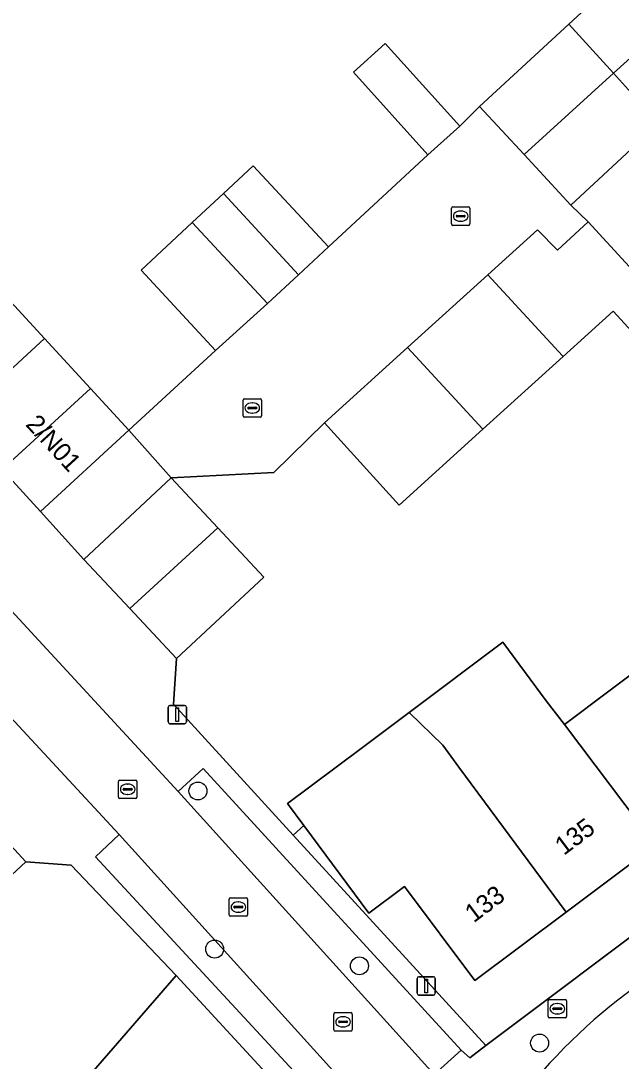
# Model space of a CAD drawing. Extents: x 158472 to 159562, y 388525 to 389606.
# Drawn here: x 159022.2 to 159054.8, y 388854.3 to 388910.9 of the extents above; entities that cross this region are included whole.
import ezdxf

# ---------------------------------------------------------------- set-up
doc = ezdxf.new("R2010")
doc.units = 0
for name, color, linetype in [('IMGEO_Boom', 7, 'Continuous'), ('IMGEO_Brandkraan', 7, 'Continuous'), ('IMGEO_Erf', 7, 'Continuous'), ('IMGEO_Kolk', 7, 'Continuous'), ('IMGEO_Lichtmast', 7, 'Continuous'), ('IMGEO_Muur', 7, 'Continuous'), ('IMGEO_Pand', 7, 'Continuous'), ('IMGEO_Pand_nummerreeks', 7, 'Continuous'), ('IMGEO_Parkeervlak_open', 7, 'Continuous'), ('IMGEO_Rijbaan_lokaal_open', 7, 'Continuous'), ('IMGEO_Voetpad_open', 7, 'Continuous')]:
    doc.layers.add(name, color=color, linetype=linetype)

msp = doc.modelspace()

# ---------------------------------------------------------------- linework, layer by layer
at = {"layer": 'IMGEO_Boom'}
for centre in [(159031.83, 388869.01), (159032.739, 388860.409), (159040.613, 388859.499), (159050.411, 388855.297)]:
    msp.add_circle(centre, 0.489, dxfattribs=at)
at = {"layer": 'IMGEO_Brandkraan'}
for p, q in [((159050.872, 388856.738), (159050.872, 388857.59)), ((159050.947, 388857.664), (159051.799, 388857.664)), ((159051.131, 388857.158), (159051.131, 388857.17)), ((159051.569, 388857.121), (159051.171, 388857.121)), ((159051.174, 388857.207), (159051.572, 388857.207)), ((159051.36, 388857.444), (159051.385, 388857.444)), ((159051.615, 388857.17), (159051.615, 388857.158)), ((159051.873, 388857.59), (159051.873, 388856.738)), ((159051.799, 388856.664), (159050.947, 388856.664)), ((159051.383, 388856.884), (159051.358, 388856.884))]:
    msp.add_line(p, q, dxfattribs=at)
for points in [[(159050.872, 388856.738), (159050.872, 388857.59)], [(159050.947, 388857.664), (159051.799, 388857.664)], [(159051.873, 388857.59), (159051.873, 388856.738)], [(159051.799, 388856.664), (159050.947, 388856.664)]]:
    msp.add_lwpolyline(points, dxfattribs=at)
for centre, radius, start, end in [((159050.949, 388857.588), 0.0765, 91.552, 178.448), ((159050.949, 388857.588), 0.0765, 91.552, 178.448), ((159051.171, 388857.167), 0.0403, 85.8775, 175.7526), ((159051.168, 388857.157), 0.0366, 178.938, 274.7102), ((159051.572, 388857.164), 0.043, 264.8664, 352.4533), ((159051.576, 388857.169), 0.0386, 1.7309, 96.639), ((159051.797, 388857.588), 0.0765, 1.552, 88.448), ((159051.797, 388857.588), 0.0765, 1.552, 88.448), ((159050.949, 388856.74), 0.0765, 181.552, 268.448), ((159050.949, 388856.74), 0.0765, 181.552, 268.448), ((159051.797, 388856.74), 0.0765, 271.552, 358.448), ((159051.797, 388856.74), 0.0765, 271.552, 358.448)]:
    msp.add_arc(centre, radius, start, end, dxfattribs=at)
for centre, major_axis, ratio, start_param, end_param in [((159051.359, 388857.164), (-0.387, 0.002), 0.722429, 4.712389, 7.853982), ((159051.384, 388857.164), (-0.39, 0.002), 0.717154, 1.570796, 4.712389)]:
    msp.add_ellipse(centre, major_axis=major_axis, ratio=ratio, start_param=start_param, end_param=end_param, dxfattribs=at)
at = {"layer": 'IMGEO_Erf'}
for points in [[(158997.065, 388911.51), (159000.837, 388907.412), (159006.203, 388901.581), (159006.027, 388900.273), (159014.937, 388890.629), (159016.222, 388891.875), (159021.022, 388896.297), (159023.484, 388893.624), (159025.982, 388890.912), (159028.075, 388888.641), (159032.79, 388892.979), (159028.735, 388897.342), (159031.517, 388899.927), (159033.216, 388901.506), (159034.832, 388903.008), (159038.924, 388898.606), (159044.34, 388903.612), (159040.28, 388908.103), (159042.012, 388909.668), (159046.071, 388905.177), (159047.144, 388906.244), (159051.996, 388910.732), (159056.776, 388915.153)], [(159056.892, 388905.314), (159052.102, 388900.883), (159053.054, 388899.965), (159057.103, 388895.546)], [(159055.425, 388894.008), (159054.409, 388895.117), (159051.69, 388892.651), (159047.327, 388888.694), (159042.774, 388884.565), (159038.715, 388889.033), (159035.965, 388886.336), (159030.379, 388886.043), (159032.915, 388883.328), (159035.419, 388880.648), (159030.671, 388876.212), (159030.494, 388873.729), (159037.009, 388866.608), (159047.484, 388855.159), (159067.671, 388870.326)], [(159056.712, 388866.061), (159051.849, 388862.421), (159046.884, 388858.706), (159043.055, 388863.822), (159041.119, 388862.372), (159037.584, 388867.135), (159036.696, 388868.331), (159040.699, 388871.328), (159043.307, 388873.28), (159048.406, 388877.097), (159050.766, 388873.917), (159051.756, 388872.635), (159056.585, 388876.249)], [(159025.441, 388852.975), (159030.636, 388858.979), (159024.943, 388864.972), (159022.471, 388865.149), (159017.646, 388860.705), (159017.52, 388860.589), (159015.056, 388863.265), (159012.581, 388865.952), (159009.531, 388858.308), (159014.028, 388854.382), (159010.166, 388849.906)]]:
    msp.add_lwpolyline(points, dxfattribs=at)
msp.add_lwpolyline([(159025.631, 388881.607), (159030.379, 388886.043), (159028.075, 388888.641), (159023.276, 388884.219)], close=True, dxfattribs=at)
at = {"layer": 'IMGEO_Kolk'}
for p, q in [((159045.619, 388899.854), (159045.619, 388900.706)), ((159045.694, 388900.78), (159046.546, 388900.78)), ((159046.62, 388900.706), (159046.62, 388899.854)), ((159045.878, 388900.274), (159045.878, 388900.286)), ((159046.316, 388900.237), (159045.918, 388900.237)), ((159045.921, 388900.323), (159046.319, 388900.323)), ((159046.107, 388900.56), (159046.132, 388900.56)), ((159046.362, 388900.286), (159046.362, 388900.274)), ((159046.546, 388899.78), (159045.694, 388899.78)), ((159046.13, 388900), (159046.105, 388900)), ((159034.283, 388889.418), (159034.283, 388890.27)), ((159034.358, 388890.344), (159035.21, 388890.344)), ((159034.771, 388890.124), (159034.796, 388890.124)), ((159035.284, 388890.27), (159035.284, 388889.418)), ((159034.542, 388889.838), (159034.542, 388889.85)), ((159034.98, 388889.801), (159034.582, 388889.801)), ((159034.585, 388889.887), (159034.983, 388889.887)), ((159034.794, 388889.564), (159034.769, 388889.564)), ((159035.026, 388889.85), (159035.026, 388889.838)), ((159035.21, 388889.344), (159034.358, 388889.344)), ((159027.584, 388869.604), (159028.436, 388869.604)), ((159027.509, 388868.678), (159027.509, 388869.53)), ((159027.768, 388869.098), (159027.768, 388869.11)), ((159028.206, 388869.061), (159027.808, 388869.061)), ((159027.811, 388869.147), (159028.209, 388869.147)), ((159027.997, 388869.384), (159028.022, 388869.384)), ((159028.252, 388869.11), (159028.252, 388869.098)), ((159028.51, 388869.53), (159028.51, 388868.678)), ((159028.436, 388868.604), (159027.584, 388868.604)), ((159028.02, 388868.824), (159027.995, 388868.824)), ((159033.529, 388862.268), (159033.529, 388863.12)), ((159033.604, 388863.194), (159034.456, 388863.194)), ((159034.017, 388862.974), (159034.042, 388862.974)), ((159034.53, 388863.12), (159034.53, 388862.268)), ((159033.788, 388862.688), (159033.788, 388862.7)), ((159034.226, 388862.651), (159033.828, 388862.651)), ((159033.831, 388862.737), (159034.229, 388862.737)), ((159034.04, 388862.414), (159034.015, 388862.414)), ((159034.272, 388862.7), (159034.272, 388862.688)), ((159034.456, 388862.194), (159033.604, 388862.194)), ((159039.221, 388856.026), (159039.221, 388856.878)), ((159039.296, 388856.952), (159040.148, 388856.952)), ((159039.709, 388856.732), (159039.734, 388856.732)), ((159040.222, 388856.878), (159040.222, 388856.026)), ((159039.48, 388856.446), (159039.48, 388856.458)), ((159039.918, 388856.409), (159039.52, 388856.409)), ((159039.523, 388856.495), (159039.921, 388856.495)), ((159039.732, 388856.172), (159039.707, 388856.172)), ((159039.964, 388856.458), (159039.964, 388856.446)), ((159040.148, 388855.952), (159039.296, 388855.952))]:
    msp.add_line(p, q, dxfattribs=at)
for points in [[(159045.619, 388899.854), (159045.619, 388900.706)], [(159045.694, 388900.78), (159046.546, 388900.78)], [(159046.62, 388900.706), (159046.62, 388899.854)], [(159046.546, 388899.78), (159045.694, 388899.78)], [(159034.283, 388889.418), (159034.283, 388890.27)], [(159034.358, 388890.344), (159035.21, 388890.344)], [(159035.284, 388890.27), (159035.284, 388889.418)], [(159035.21, 388889.344), (159034.358, 388889.344)], [(159027.584, 388869.604), (159028.436, 388869.604)], [(159027.509, 388868.678), (159027.509, 388869.53)], [(159028.51, 388869.53), (159028.51, 388868.678)], [(159028.436, 388868.604), (159027.584, 388868.604)], [(159033.529, 388862.268), (159033.529, 388863.12)], [(159033.604, 388863.194), (159034.456, 388863.194)], [(159034.53, 388863.12), (159034.53, 388862.268)], [(159034.456, 388862.194), (159033.604, 388862.194)], [(159039.221, 388856.026), (159039.221, 388856.878)], [(159039.296, 388856.952), (159040.148, 388856.952)], [(159040.222, 388856.878), (159040.222, 388856.026)], [(159040.148, 388855.952), (159039.296, 388855.952)]]:
    msp.add_lwpolyline(points, dxfattribs=at)
for centre, radius, start, end in [((159045.696, 388900.704), 0.0765, 91.552, 178.448), ((159045.696, 388900.704), 0.0765, 91.552, 178.448), ((159046.544, 388900.704), 0.0765, 1.552, 88.448), ((159046.544, 388900.704), 0.0765, 1.552, 88.448), ((159045.918, 388900.283), 0.0403, 85.8775, 175.7526), ((159045.915, 388900.273), 0.0366, 178.938, 274.7102), ((159046.319, 388900.28), 0.043, 264.8664, 352.4533), ((159046.323, 388900.285), 0.0386, 1.7309, 96.639), ((159045.696, 388899.856), 0.0765, 181.552, 268.448), ((159045.696, 388899.856), 0.0765, 181.552, 268.448), ((159046.544, 388899.856), 0.0765, 271.552, 358.448), ((159046.544, 388899.856), 0.0765, 271.552, 358.448), ((159034.36, 388890.268), 0.0765, 91.552, 178.448), ((159034.36, 388890.268), 0.0765, 91.552, 178.448), ((159035.208, 388890.268), 0.0765, 1.552, 88.448), ((159035.208, 388890.268), 0.0765, 1.552, 88.448), ((159034.36, 388889.42), 0.0765, 181.552, 268.448), ((159034.36, 388889.42), 0.0765, 181.552, 268.448), ((159034.582, 388889.847), 0.0403, 85.8775, 175.7526), ((159034.579, 388889.837), 0.0366, 178.938, 274.7102), ((159034.983, 388889.844), 0.043, 264.8664, 352.4533), ((159034.987, 388889.849), 0.0386, 1.7309, 96.639), ((159035.208, 388889.42), 0.0765, 271.552, 358.448), ((159035.208, 388889.42), 0.0765, 271.552, 358.448), ((159027.586, 388869.528), 0.0765, 91.552, 178.448), ((159027.586, 388869.528), 0.0765, 91.552, 178.448), ((159028.434, 388869.528), 0.0765, 1.552, 88.448), ((159028.434, 388869.528), 0.0765, 1.552, 88.448), ((159027.808, 388869.107), 0.0403, 85.8775, 175.7526), ((159027.805, 388869.097), 0.0366, 178.938, 274.7102), ((159028.209, 388869.104), 0.043, 264.8664, 352.4533), ((159028.213, 388869.109), 0.0386, 1.7309, 96.639), ((159027.586, 388868.68), 0.0765, 181.552, 268.448), ((159027.586, 388868.68), 0.0765, 181.552, 268.448), ((159028.434, 388868.68), 0.0765, 271.552, 358.448), ((159028.434, 388868.68), 0.0765, 271.552, 358.448), ((159033.606, 388863.118), 0.0765, 91.552, 178.448), ((159033.606, 388863.118), 0.0765, 91.552, 178.448), ((159034.454, 388863.118), 0.0765, 1.552, 88.448), ((159034.454, 388863.118), 0.0765, 1.552, 88.448), ((159033.606, 388862.27), 0.0765, 181.552, 268.448), ((159033.606, 388862.27), 0.0765, 181.552, 268.448), ((159033.828, 388862.697), 0.0403, 85.8775, 175.7526), ((159033.825, 388862.687), 0.0366, 178.938, 274.7102), ((159034.229, 388862.694), 0.043, 264.8664, 352.4533), ((159034.233, 388862.699), 0.0386, 1.7309, 96.639), ((159034.454, 388862.27), 0.0765, 271.552, 358.448), ((159034.454, 388862.27), 0.0765, 271.552, 358.448), ((159039.298, 388856.876), 0.0765, 91.552, 178.448), ((159039.298, 388856.876), 0.0765, 91.552, 178.448), ((159040.146, 388856.876), 0.0765, 1.552, 88.448), ((159040.146, 388856.876), 0.0765, 1.552, 88.448), ((159039.298, 388856.028), 0.0765, 181.552, 268.448), ((159039.298, 388856.028), 0.0765, 181.552, 268.448), ((159039.52, 388856.455), 0.0403, 85.8775, 175.7526), ((159039.517, 388856.445), 0.0366, 178.938, 274.7102), ((159039.921, 388856.452), 0.043, 264.8664, 352.4533), ((159039.925, 388856.457), 0.0386, 1.7309, 96.639), ((159040.146, 388856.028), 0.0765, 271.552, 358.448), ((159040.146, 388856.028), 0.0765, 271.552, 358.448)]:
    msp.add_arc(centre, radius, start, end, dxfattribs=at)
for centre, major_axis, ratio, start_param, end_param in [((159046.106, 388900.28), (-0.387, 0.002), 0.722429, 4.712389, 7.853982), ((159046.131, 388900.28), (-0.39, 0.002), 0.717154, 1.570796, 4.712389), ((159034.77, 388889.844), (-0.387, 0.002), 0.722429, 4.712389, 7.853982), ((159034.795, 388889.844), (-0.39, 0.002), 0.717154, 1.570796, 4.712389), ((159027.996, 388869.104), (-0.387, 0.002), 0.722429, 4.712389, 7.853982), ((159028.021, 388869.104), (-0.39, 0.002), 0.717154, 1.570796, 4.712389), ((159034.016, 388862.694), (-0.387, 0.002), 0.722429, 4.712389, 7.853982), ((159034.041, 388862.694), (-0.39, 0.002), 0.717154, 1.570796, 4.712389), ((159039.708, 388856.452), (-0.387, 0.002), 0.722429, 4.712389, 7.853982), ((159039.733, 388856.452), (-0.39, 0.002), 0.717154, 1.570796, 4.712389)]:
    msp.add_ellipse(centre, major_axis=major_axis, ratio=ratio, start_param=start_param, end_param=end_param, dxfattribs=at)
at = {"layer": 'IMGEO_Lichtmast'}
for p, q in [((159030.208, 388872.767), (159030.208, 388873.567)), ((159030.208, 388873.567), (159030.208, 388872.767)), ((159030.308, 388873.667), (159031.098, 388873.667)), ((159031.098, 388873.667), (159030.308, 388873.667)), ((159031.198, 388873.567), (159031.198, 388872.767)), ((159031.198, 388872.767), (159031.198, 388873.567)), ((159031.098, 388872.667), (159030.308, 388872.667)), ((159030.308, 388872.667), (159031.098, 388872.667)), ((159043.845, 388858.907), (159044.635, 388858.907)), ((159044.635, 388858.907), (159043.845, 388858.907)), ((159043.745, 388858.007), (159043.745, 388858.807)), ((159043.745, 388858.807), (159043.745, 388858.007)), ((159044.735, 388858.807), (159044.735, 388858.007)), ((159044.735, 388858.007), (159044.735, 388858.807)), ((159044.635, 388857.907), (159043.845, 388857.907)), ((159043.845, 388857.907), (159044.635, 388857.907))]:
    msp.add_line(p, q, dxfattribs=at)
for points in [[(159030.628, 388873.542), (159030.778, 388873.542), (159030.778, 388872.792), (159030.628, 388872.792), (159030.628, 388873.542)], [(159044.165, 388858.782), (159044.315, 388858.782), (159044.315, 388858.032), (159044.165, 388858.032), (159044.165, 388858.782)]]:
    msp.add_lwpolyline(points, dxfattribs=at)
for centre, start, end in [((159030.308, 388873.567), 90, 180), ((159030.308, 388873.567), 90, 180), ((159031.098, 388873.567), 0, 90), ((159031.098, 388873.567), 360, 90), ((159030.308, 388872.767), 180, 270), ((159030.308, 388872.767), 180, 270), ((159031.098, 388872.767), 270, 0), ((159031.098, 388872.767), 270, 0), ((159043.845, 388858.807), 90, 180), ((159043.845, 388858.807), 90, 180), ((159044.635, 388858.807), 0, 90), ((159044.635, 388858.807), 360, 90), ((159043.845, 388858.007), 180, 270), ((159043.845, 388858.007), 180, 270), ((159044.635, 388858.007), 270, 0), ((159044.635, 388858.007), 270, 0)]:
    msp.add_arc(centre, 0.1, start, end, dxfattribs=at)
at = {"layer": 'IMGEO_Muur'}
for points in [[(159037.009, 388866.608), (159030.494, 388873.729)], [(159037.584, 388867.135), (159037.009, 388866.608)], [(159022.471, 388865.149), (159024.943, 388864.972), (159030.636, 388858.979)]]:
    msp.add_lwpolyline(points, dxfattribs=at)
at = {"layer": 'IMGEO_Pand'}
for points in [[(159059.274, 388912.453), (159057.097, 388914.806), (159056.776, 388915.153), (159051.996, 388910.732), (159054.43, 388908.05)], [(159059.274, 388912.453), (159054.43, 388908.05), (159056.88, 388905.33), (159056.892, 388905.314), (159061.734, 388909.793)], [(159049.561, 388903.63), (159054.43, 388908.05), (159051.996, 388910.732), (159047.144, 388906.244)], [(159046.071, 388905.177), (159042.012, 388909.668), (159040.28, 388908.103), (159044.34, 388903.612)], [(159049.561, 388903.63), (159052.102, 388900.883), (159056.892, 388905.314), (159056.88, 388905.33), (159054.43, 388908.05)], [(159037.297, 388897.093), (159038.924, 388898.606), (159034.832, 388903.008), (159033.216, 388901.506), (159033.23, 388901.49)], [(159037.297, 388897.093), (159033.23, 388901.49), (159033.216, 388901.506), (159031.517, 388899.927), (159035.61, 388895.525)], [(159031.517, 388899.927), (159028.735, 388897.342), (159032.79, 388892.979), (159035.61, 388895.525)], [(159047.598, 388897.093), (159051.66, 388892.69), (159051.69, 388892.651), (159054.409, 388895.117), (159055.425, 388894.008), (159057.103, 388895.546), (159053.054, 388899.965), (159051.375, 388898.427), (159050.287, 388899.534)], [(159047.598, 388897.093), (159043.227, 388893.127), (159047.327, 388888.694), (159051.69, 388892.651), (159051.66, 388892.69)], [(159023.484, 388893.624), (159021.022, 388896.297), (159016.222, 388891.875), (159018.687, 388889.199)], [(159025.982, 388890.912), (159023.484, 388893.624), (159018.687, 388889.199), (159021.183, 388886.49)], [(159043.227, 388893.127), (159038.715, 388889.033), (159042.774, 388884.565), (159047.327, 388888.694)], [(159025.982, 388890.912), (159021.183, 388886.49), (159023.276, 388884.219), (159028.075, 388888.641)], [(159032.915, 388883.328), (159030.379, 388886.043), (159025.631, 388881.607), (159028.124, 388878.939)], [(159032.915, 388883.328), (159028.124, 388878.939), (159030.671, 388876.212), (159035.419, 388880.648)], [(159051.849, 388862.421), (159056.712, 388866.061), (159051.756, 388872.635), (159050.766, 388873.917), (159048.406, 388877.097), (159043.307, 388873.28), (159045.14, 388871.51), (159046.01, 388870.3)], [(159061.51, 388869.651), (159056.585, 388876.249), (159051.756, 388872.635), (159056.712, 388866.061)], [(159051.849, 388862.421), (159046.01, 388870.3), (159045.14, 388871.51), (159043.307, 388873.28), (159040.699, 388871.328), (159036.696, 388868.331), (159037.584, 388867.135), (159041.119, 388862.372), (159043.055, 388863.822), (159046.884, 388858.706)], [(159022.471, 388865.149), (159019.99, 388867.843), (159015.056, 388863.265), (159017.52, 388860.589), (159017.646, 388860.705)], [(159024.833, 388852.272), (159033.849, 388844.529), (159037.849, 388849.116), (159035.445, 388851.212), (159036.588, 388852.524), (159030.636, 388858.979), (159025.441, 388852.975)]]:
    msp.add_lwpolyline(points, close=True, dxfattribs=at)
at = {"layer": 'IMGEO_Parkeervlak_open'}
for points in [[(159032.108, 388870.238), (159030.762, 388868.976), (159044.684, 388853.597), (159046.143, 388854.918)], [(159027.544, 388866.648), (159026.258, 388865.425), (159040.611, 388849.91), (159041.757, 388850.948)]]:
    msp.add_lwpolyline(points, close=True, dxfattribs=at)
at = {"layer": 'IMGEO_Rijbaan_lokaal_open'}
for points in [[(159047.598, 388897.093), (159050.287, 388899.534), (159051.375, 388898.427), (159053.054, 388899.965), (159052.102, 388900.883), (159049.561, 388903.63), (159047.144, 388906.244), (159046.071, 388905.177), (159044.34, 388903.612), (159038.924, 388898.606), (159037.297, 388897.093), (159035.61, 388895.525), (159032.79, 388892.979), (159028.075, 388888.641), (159030.379, 388886.043), (159035.965, 388886.336), (159038.715, 388889.033), (159043.227, 388893.127)], [(159011.707, 388889.621), (159012.963, 388890.865), (159006.407, 388898.008), (159004.406, 388896.221), (159002.069, 388894.135), (159027.544, 388866.648), (159041.757, 388850.948), (159044.684, 388853.597), (159030.762, 388868.976)]]:
    msp.add_lwpolyline(points, close=True, dxfattribs=at)
msp.add_arc((159074.227, 388832.759), 31.644, 125.1302, 141.4165, dxfattribs=at)
at = {"layer": 'IMGEO_Voetpad_open'}
for points in [[(159030.671, 388876.212), (159028.124, 388878.939), (159025.631, 388881.607), (159023.276, 388884.219), (159021.183, 388886.49), (159018.687, 388889.199), (159016.222, 388891.875), (159014.937, 388890.629), (159006.027, 388900.273), (159006.203, 388901.581), (159000.837, 388907.412), (158997.065, 388911.51), (158995.082, 388913.591)], [(158993.958, 388912.41), (158993.095, 388911.436), (158991.758, 388909.738), (158994.21, 388907.064), (158997.305, 388909.881), (159005.184, 388901.225), (159002.168, 388898.532), (159004.406, 388896.221), (159006.407, 388898.008), (159012.963, 388890.865), (159011.707, 388889.621), (159030.762, 388868.976), (159032.108, 388870.238), (159046.143, 388854.918), (159046.611, 388854.503), (159047.484, 388855.159), (159037.009, 388866.608), (159030.494, 388873.729), (159030.671, 388876.212)], [(158988.017, 388905.027), (158988.788, 388904.188), (159000, 388891.989), (159009.691, 388881.445), (159014.98, 388875.691), (159014.649, 388873.584), (159017.532, 388870.512), (159019.99, 388867.843), (159022.471, 388865.149), (159024.943, 388864.972), (159030.636, 388858.979), (159036.588, 388852.524), (159039.702, 388849.044), (159042.094, 388846.371), (159043.009, 388847.412), (159040.611, 388849.91), (159026.258, 388865.425), (159027.544, 388866.648), (159002.069, 388894.135)], [(159094.08, 388890.466), (159089.848, 388886.988), (159067.671, 388870.326), (159047.484, 388855.159), (159046.611, 388854.503), (159046.143, 388854.918), (159044.684, 388853.597), (159041.757, 388850.948), (159040.611, 388849.91), (159043.009, 388847.412), (159042.094, 388846.371), (159034.383, 388837.602), (159004.229, 388805.879), (159005.956, 388804.315), (159007.95, 388802.429), (159009.905, 388799.335)]]:
    msp.add_lwpolyline(points, dxfattribs=at)
msp.add_arc((159074.227, 388832.759), 31.644, 125.1302, 141.4165, dxfattribs=at)

# ---------------------------------------------------------------- texts
at = {"layer": 'IMGEO_Pand_nummerreeks'}
for s, rotation, p in [('2/N01', 312.594, (159022.413, 388888.917)), ('135', 36.8089, (159051.724, 388865.475)), ('133', 36.8089, (159046.826, 388861.809))]:
    msp.add_text(s, height=1, rotation=rotation, dxfattribs=at).set_placement(p)

doc.saveas('drawing.dxf')
